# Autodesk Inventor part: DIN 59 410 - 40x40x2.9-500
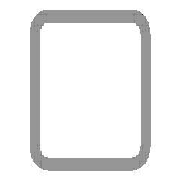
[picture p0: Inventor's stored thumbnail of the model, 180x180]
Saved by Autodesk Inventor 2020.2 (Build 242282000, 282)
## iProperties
Manager: www.cadconsulting.pl
Company: Fabian Stasiak CAD Consulting
_CCFamilyMember: 10
_CCFamilyDisplayName: DIN 59410 (Kwadrat) - Rurki stalowe o przekroju kwadratowym formowane na gorąco
_FrameMemberDoc: Frame Member File
_Version: 15.0.0
_GetPNFromCC: 1
Created: 2015-01
Part Number: DIN 59 410 - 40x40x2.9-500
Material: Stal, miękka
Description: Rurki stalowe o przekroju kwadratowym formowane na gorąco
Document SubType Name: Modellieren
Standard: DIN
Designer: F.Stasiak
Standards Organization: DIN
Language: pl-PL
Size Designation: 40x40x2.9
Categories: <MemberInstance><Categories><Category DisplayName="Kształtowniki konstrukcyjne" InternalName="089c4875-fa83-4c05-b084-43b9cc11f5ed" Mnemonic="GRDR"><CategoryPar
Stock Number: 40x40x2.9
Density: 7.85 g/cm^3
Appearance: Częściowo polerowana
Catalog Web Link: www.expertbooks.pl
IsCustomPart: 1
G_L: 500,000 mm
G_W: 40,000 mm
G_H: 40,000 mm
Author: F.Stasiak
Subject: Zbiór ćwiczeń. Autodesk Inventor 2020. Kurs Professional
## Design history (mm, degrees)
node "Płaszczyzna początkowa"
node "Płaszczyzna końcowa"
sketch "Szkic"
  geometry: L1 (-14.2, 20)-(14.2, 20); L2 (20, 14.2)-(20, -14.2); L3 (14.2, -20)-(-14.2, -20); L4 (-20, -14.2)-(-20, 14.2); L5 (-29.682, 0)-(29.682, 0) reference; L6 (0, -29.682)-(0, 29.682) reference; L7 (-14.2, 17.1)-(14.2, 17.1); L8 (17.1, 14.2)-(17.1, -14.2); L9 (14.2, -17.1)-(-14.2, -17.1); L10 (-17.1, -14.2)-(-17.1, 14.2); A1 r 5.8 centre (-14.2, 14.2) between (-14.2, 20) and (-20, 14.2); A2 r 5.8 centre (14.2, 14.2) between (20, 14.2) and (14.2, 20); A3 r 5.8 centre (14.2, -14.2) between (14.2, -20) and (20, -14.2); A4 r 5.8 centre (-14.2, -14.2) between (-20, -14.2) and (-14.2, -20); A5 r 2.9 centre (-14.2, 14.2) between (-14.2, 17.1) and (-17.1, 14.2); A6 r 2.9 centre (14.2, 14.2) between (17.1, 14.2) and (14.2, 17.1); A7 r 2.9 centre (14.2, -14.2) between (14.2, -17.1) and (17.1, -14.2); A8 r 2.9 centre (-14.2, -14.2) between (-17.1, -14.2) and (-14.2, -17.1); 3 further points
  constraints: 16 end point, 16 point on circle, 8 centre point, 8 tangent, 6 point on line, 4 parallel, 3 equal radius, 3 perpendicular, 1 horizontal, 7 other
  dimensions: "b" = 40 distance of point (-20, 20) point (20, 20); "msp_r" = 5.8 radius of A1 (= 2 x ParT); "d8" = 20 distance between parallel lines of L4 L6 (= d9); "d9" = 20 distance between parallel lines of L3 L5 (= 0.5 x b); "d10" = 2.9 distance between parallel lines of L3 L9 (= ParT)
extrude "Bryła" new body sketch "Szkic" taper "d4" = 0 deg; stored distance "NLG" = 10
node "Driven Length"
  sketch "Sketch2"
    geometry: L1 (0, 0)-(10, 0) reference
    constraints: 2 end point, 1 horizontal
  workplane "Work Plane3"
  sketch "Sketch3"
    geometry: L1 (-2, 0)-(12, 0) reference; L2 (-2, 500)-(12, 500) reference
    dimensions: "d14" = 500 distance between parallel lines of L1 L2 (derived)
body "Solid1"
other parameters: "ParT" = 2.9, "G_OFFSET_START" = 0 [user parameter; used in 1 equation term], "G_OFFSET_END" = 0 [user parameter; used in 1 equation term], "d11" = 0 (computed from G_OFFSET_START), "G_L" = 500 (= d14) [user parameter], "d13" = 90 deg
